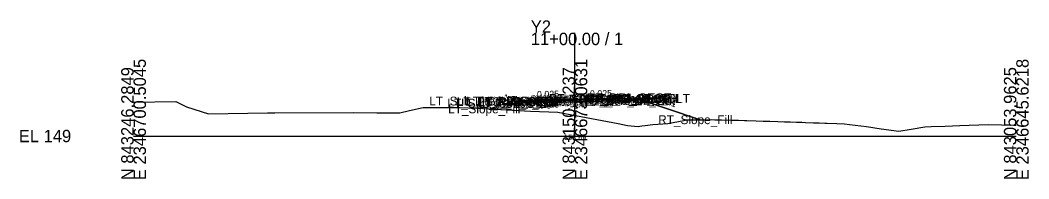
# Model space of a CAD drawing. Extents: x -26 to 2346977, y -10 to 843253.
# Drawn here: x -25.7 to 202.8, y 490.3 to 526.2 of the extents above; entities that cross this region are included whole.
import ezdxf

# ---------------------------------------------------------------- set-up
doc = ezdxf.new("R2010")
doc.units = 0
for name, color, linetype in [('Default', 7, 'Continuous'), ('Exist Cross Section Cell', 7, 'Continuous'), ('Exist XS Center Line Elevation Label', 7, 'Continuous'), ('Exist XS Ground Line', 7, 'Continuous'), ('Prop CMT Pvmt Course 1', 7, 'Continuous'), ('Prop CMT Pvmt Course 2', 7, 'Continuous'), ('Prop CMT Pvmt Course 3', 7, 'Continuous'), ('Prop CMT Pvmt Surface', 7, 'Continuous'), ('Prop CMT Pvmt Surface Shoulder', 7, 'Continuous'), ('Prop CMT Shld Paved Course 1', 7, 'Continuous'), ('Prop CMT Shld Paved Course 2', 7, 'Continuous'), ('Prop CMT Shld Paved Course 3', 7, 'Continuous'), ('Prop CMT Slope Grass', 7, 'Continuous'), ('Prop CMT Subgrade Earthwork', 7, 'Continuous'), ('Prop XS Earthwork Shape', 7, 'Continuous'), ('Prop XS SE Text', 7, 'Continuous'), ('Prop XS Side Slope Text', 7, 'Continuous'), ('Scratch_Level_2', 7, 'Continuous')]:
    doc.layers.add(name, color=color, linetype=linetype)

msp = doc.modelspace()

# ---------------------------------------------------------------- linework, layer by layer
at = {"layer": 'Exist Cross Section Cell'}
for p, q in [((100, 500), (100, 523.39)), ((0, 500), (100, 500)), ((100, 500), (200, 500))]:
    msp.add_line(p, q, dxfattribs=at)
at = {"layer": 'Exist XS Ground Line'}
msp.add_lwpolyline([(0, 507.65), (9.55, 507.8), (12, 506.61), (16.96, 505), (30.31, 505.24), (30.92, 505.25), (32.04, 505.25), (49.9, 505.32), (55.09, 505.28), (60.36, 505.24), (62.52, 505.75), (65.62, 506.48), (73.9, 506.43), (77.74, 506.3), (89.94, 505.65), (96.12, 505.41), (100.15, 504.67), (109.8, 502.82), (111.93, 502.4), (114.31, 502.19), (114.68, 502.23), (115.17, 502.28), (115.95, 502.39), (117.66, 502.62), (121.07, 502.85), (124.64, 503.55), (125.28, 503.68), (128.09, 503.69), (129.27, 503.7), (130.54, 503.7), (130.89, 503.71), (131.68, 503.7), (133.19, 503.66), (135.33, 503.61), (136.1, 503.58), (137.06, 503.56), (138.41, 503.52), (138.95, 503.5), (141.03, 503.44), (142.62, 503.39), (143.63, 503.35), (144.19, 503.34), (145.97, 503.29), (147.49, 503.24), (148.79, 503.19), (150.22, 503.15), (151.4, 503.11), (152.27, 503.08), (154.02, 503.02), (154.32, 503.01), (155.32, 502.97), (156.61, 502.92), (157.15, 502.9), (159.34, 502.8), (161.09, 502.73), (162.23, 502.6), (166.07, 502.18), (169.42, 501.61), (173.42, 501.12), (176.19, 501.54), (179.28, 502.11), (180.75, 502.14), (183.89, 502.26), (187.17, 502.37), (193.6, 502.6), (199.64, 502.49), (200, 502.49)], dxfattribs=at)
at = {"layer": 'Prop CMT Pvmt Course 1'}
for p, q in [((100, 508.35), (88, 508.05)), ((88, 507.8), (100, 508.1)), ((88, 508.05), (88, 507.8)), ((100, 508.35), (112, 508.65)), ((112, 508.4), (100, 508.1)), ((100, 508.1), (100, 508.35)), ((100, 508.1), (100, 508.35)), ((100, 508.1), (100, 508.22)), ((100, 508.22), (100, 508.22)), ((100, 508.22), (100, 508.1)), ((100, 508.1), (100, 508.22)), ((100, 508.22), (100, 508.22)), ((100, 508.22), (100, 508.1)), ((100, 508.1), (100, 508.1)), ((100, 508.1), (100, 508.1)), ((112, 508.65), (112, 508.4))]:
    msp.add_line(p, q, dxfattribs=at)
at = {"layer": 'Prop CMT Pvmt Course 2'}
for p, q in [((88, 507.8), (100, 508.1)), ((100, 508.1), (88, 507.8)), ((88, 507.8), (88, 507.8)), ((112, 508.4), (100, 508.1)), ((100, 508.1), (112, 508.4)), ((100, 508.1), (100, 508.1)), ((100, 508.1), (100, 508.1)), ((112, 508.4), (112, 508.4))]:
    msp.add_line(p, q, dxfattribs=at)
at = {"layer": 'Prop CMT Pvmt Course 3'}
for p, q in [((100, 508.1), (88, 507.8)), ((88, 507.8), (88, 507.47)), ((88, 507.47), (100, 507.77)), ((100, 508.1), (112, 508.4)), ((100, 507.77), (100, 508.1)), ((100, 507.77), (100, 508.1)), ((112, 508.07), (100, 507.77)), ((112, 508.4), (112, 508.07))]:
    msp.add_line(p, q, dxfattribs=at)
at = {"layer": 'Prop CMT Pvmt Surface'}
for q in [(88, 508.05), (112, 508.65)]:
    msp.add_line((100, 508.35), q, dxfattribs=at)
at = {"layer": 'Prop CMT Pvmt Surface Shoulder'}
for p, q in [((88, 508.05), (88, 508.05)), ((112, 508.65), (112, 508.65))]:
    msp.add_line(p, q, dxfattribs=at)
at = {"layer": 'Prop CMT Shld Paved Course 1'}
for p, q in [((88, 508.05), (87.74, 507.79)), ((87.74, 507.79), (88, 507.8)), ((88, 508.05), (88, 508.05)), ((88, 507.8), (88, 508.05)), ((112, 508.65), (112, 508.65)), ((112, 508.65), (112.26, 508.39)), ((112, 508.4), (112, 508.65)), ((112.26, 508.39), (112, 508.4))]:
    msp.add_line(p, q, dxfattribs=at)
at = {"layer": 'Prop CMT Shld Paved Course 2'}
for p, q in [((88, 507.8), (87.74, 507.79)), ((87.74, 507.79), (88, 507.8)), ((87.74, 507.79), (87.74, 507.79)), ((88, 507.8), (88, 507.8)), ((112, 508.4), (112.26, 508.39)), ((112.26, 508.39), (112, 508.4)), ((112, 508.4), (112, 508.4)), ((112.26, 508.39), (112.26, 508.39))]:
    msp.add_line(p, q, dxfattribs=at)
at = {"layer": 'Prop CMT Shld Paved Course 3'}
for p, q in [((87.24, 507.78), (86.9, 507.44)), ((86.9, 507.44), (88, 507.47)), ((87.74, 507.79), (87.24, 507.78)), ((88, 507.8), (87.74, 507.79)), ((88, 507.47), (88, 507.8)), ((112, 508.4), (112.26, 508.39)), ((112, 508.07), (112, 508.4)), ((113.1, 508.04), (112, 508.07)), ((112.26, 508.39), (112.76, 508.38)), ((112.76, 508.38), (113.1, 508.04))]:
    msp.add_line(p, q, dxfattribs=at)
at = {"layer": 'Prop CMT Slope Grass'}
for p, q in [((86, 507.89), (80.75, 506.14)), ((88, 508.05), (86, 507.89)), ((112, 508.65), (114, 508.49)), ((114, 508.49), (128.4, 503.69))]:
    msp.add_line(p, q, dxfattribs=at)
at = {"layer": 'Prop CMT Subgrade Earthwork'}
for p, q in [((86.9, 507.44), (86.43, 507.92)), ((88, 507.47), (86.9, 507.44)), ((100, 507.77), (88, 507.47)), ((100, 507.77), (112, 508.07)), ((112, 508.07), (113.1, 508.04)), ((113.1, 508.04), (113.57, 508.52))]:
    msp.add_line(p, q, dxfattribs=at)
at = {"layer": 'Prop XS Earthwork Shape'}
msp.add_lwpolyline([(80.75, 506.14), (89.94, 505.65), (96.12, 505.41), (100.15, 504.67), (109.8, 502.82), (111.93, 502.4), (114.31, 502.19), (114.68, 502.23), (115.17, 502.28), (115.95, 502.39), (117.66, 502.62), (121.07, 502.85), (124.64, 503.55), (125.28, 503.68), (128.09, 503.69), (128.4, 503.69), (114, 508.49), (113.57, 508.52), (113.1, 508.04), (112, 508.07), (100, 507.77), (88, 507.47), (86.9, 507.44), (86.43, 507.92), (86, 507.89)], close=True, dxfattribs=at)

# ---------------------------------------------------------------- texts
at = {"layer": 'Default'}
msp.add_text('-', height=0.0001, dxfattribs=at).set_placement((0, 500))
at = {"layer": 'Exist Cross Section Cell'}
for s, p in [('Y2', (90, 523.39)), ('11+00.00 / 1', (90, 520.59)), ('EL 149', (-26, 498.6))]:
    msp.add_text(s, height=2.8, dxfattribs=at).set_placement(p)
for s, p in [('E 2346700.5045', (2.8, 490)), ('E 2346673.0631', (102.8, 490)), ('E 2346645.6218', (202.8, 490)), ('N 843246.2849', (0, 490)), ('N 843150.1237', (100, 490)), ('N 843053.9625', (200, 490))]:
    msp.add_text(s, height=2.8, rotation=90, dxfattribs=at).set_placement(p)
at = {"layer": 'Exist XS Center Line Elevation Label'}
msp.add_text('153.69', height=1.2, dxfattribs=at).set_placement((97.52, 499.09))
at = {"layer": 'Prop XS SE Text'}
for p in [(91.42, 508.66), (103.42, 508.82)]:
    msp.add_text('0.025', height=1.5, rotation=1.4321, dxfattribs=at).set_placement(p)
at = {"layer": 'Prop XS Side Slope Text'}
for rotation, p in [(18.4332, (82.72, 507.31)), (341.5668, (120.1, 507.36))]:
    msp.add_text('3:1', height=1.5, rotation=rotation, dxfattribs=at).set_placement(p)
at = {"layer": 'Scratch_Level_2'}
for s, p in [('RT_Sub_Trench_Out_DLT', (94.09, 507.52)), ('RT_PV1_OEOT', (102.69, 507.65)), ('RT_PS1_OEOP', (102.76, 507.65)), ('LT_Sub_Trench_Out_DLT', (66.99, 506.92)), ('LT_Sub_Trench_Out', (71.11, 506.44)), ('LT_PS3_Shelf_Out', (73.23, 506.78)), ('LT_GS_OS_CTL', (75.37, 506.89)), ('LT_PS3_OEOP', (77.98, 506.79)), ('LT_PS2_OEOP', (77.98, 506.79)), ('LT_Sub_OEOT', (78.08, 506.47)), ('LT_PV3_OEOT', (78.17, 506.8)), ('LT_PV2_OEOT', (78.17, 506.8)), ('LT_PV1_OEOT', (78.74, 507.05)), ('LT_PS1_OEOP', (78.8, 507.05)), ('RT_Sub_OEEOP', (89.17, 506.77)), ('LT_Sub_OEEOP', (89.21, 506.77)), ('RT_PV2_OEEOP', (89.26, 507.1)), ('RT_PV3_OEEOP', (89.26, 507.1)), ('LT_PV2_OEEOP', (89.31, 507.1)), ('LT_PV3_OEEOP', (89.31, 507.1)), ('RT_PV1_OEEOP', (89.83, 507.22)), ('LT_PV1_OEEOP', (89.87, 507.22)), ('RT_PV2_IEEOP', (89.91, 507.1)), ('LT_PV2_IEEOP', (89.95, 507.1)), ('RT_PV1_IEEOP', (90.47, 507.22)), ('LT_PV1_IEEOP', (90.52, 507.22)), ('PV2_PGL', (93.91, 507.1)), ('PV1_PGL', (94.47, 507.35)), ('RT_Sub_Trench_Out', (97.25, 507.04)), ('RT_PS3_Shelf_Out', (98.69, 507.38)), ('RT_Sub_OEOT', (102.03, 507.07)), ('RT_PV3_OEOT', (102.13, 507.4)), ('RT_PV2_OEOT', (102.13, 507.4)), ('RT_PS3_OEOP', (102.44, 507.39)), ('RT_PS2_OEOP', (102.44, 507.39)), ('RT_GS_OS_CTL', (103.32, 507.49)), ('LT_Slope_Fill', (71.27, 505.14)), ('RT_Slope_Fill', (118.87, 502.69))]:
    msp.add_text(s, height=2, dxfattribs=at).set_placement(p)

doc.saveas('drawing.dxf')
